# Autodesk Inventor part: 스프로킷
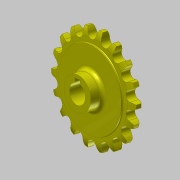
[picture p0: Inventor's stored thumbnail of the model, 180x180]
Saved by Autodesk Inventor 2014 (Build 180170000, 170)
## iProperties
Created: 2016-03
Part Number: 스프로킷
Material: 강철, 탄소
Document SubType Name: Modeling
Designer: mduedu
Density: 7.87 g/cm^3
Mass: 301.818 g
Surface Area: 124.882 cm^2
Volume: 38.3505 cm^3
Appearance: Smooth - Yellow
Author: mduedu
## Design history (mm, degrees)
sketch "스케치1"
  geometry: L1 (0, 5)-(29.5, 5); L2 (29.5, 5)-(29.5, 4.1); L3 (30, 3.6)-(33.625, 3.6); L4 (40, 2)-(40, 0); L5 (40, 0)-(0, 0); L6 (0, 0)-(0, 5); L7 (0, -5)-(29.5, -5); L8 (29.5, -5)-(29.5, -4.1); L9 (30, -3.6)-(33.625, -3.6); L10 (40, -2)-(40, 0); L11 (0, 0)-(0, -5); A1 r 13.5 centre (33.625, -9.9) between (40, 2) and (33.625, 3.6); A2 r 13.5 centre (33.625, 9.9) between (33.625, -3.6) and (40, -2); A3 r 0.5 centre (30, 4.1) between (29.5, 4.1) and (30, 3.6); A4 r 0.5 centre (30, -4.1) between (30, -3.6) and (29.5, -4.1); 2 further points
  constraints: 22 end point, 8 point on circle, 6 symmetric about line, 5 tangent, 4 centre point, 4 parallel, 4 point on line, 1 equal radius, 1 horizontal, 1 perpendicular, 1 other
  dimensions: "d0" = 80 diameter of L4 L6; "d2" = 59 diameter of L2 L6; "d3" = 1.6 vertical distance of L4.start L3.end; "d4" = 3.6 distance from line of L4.end L3; "d5" = 5 distance between parallel lines of L5 L1; "d6" = 13.5 radius of A1; "d15" = 0.5 radius of A3
revolve "회전1" sketch "스케치1" stored, may be unused: angle "d7" = 90 deg
sketch "스케치2" dims "d8" = 65.2, "d11" = 80
  geometry: L1 (0, 0)-(0, 32.6); A1 r 36.57 centre (0, 0) between (-16.231, 32.771) and (0, 36.57); A2 r 3.97 centre (0, 36.57) between (-3.866, 35.665) and (0, 32.6); A3 r 12.7 centre (-16.231, 32.771) between (-3.866, 35.665) and (-5.534, 39.615); A4 r 12.7 centre (16.231, 32.771) between (5.534, 39.615) and (3.866, 35.665); A5 r 3.97 centre (0, 36.57) between (0, 32.6) and (3.866, 35.665); A6 r 40 centre (0, 0) between (5.534, 39.615) and (-5.534, 39.615); 2 further points
  constraints: 12 point on circle, 6 centre point, 4 coincident, 3 symmetric about line, 2 end point, 1 point on line, 1 tangent, 1 vertical, 1 vertical alignment, 7 other
  dimensions: "d10" = 73.14 diameter of A1; "d12" = 12.7 radius of A3
extrude "돌출1" cut sketch "스케치2" stored distance "d13" = 10; taper "d14" = 0 deg
sketch "스케치3"
  geometry: C1 r 12.5 at (0, 0); 1 further point
  constraints: 1 centre point, 1 coincident
  dimensions: "d19" = 25 diameter of C1
extrude "돌출2" join sketch "스케치3" distance "d20" = 10; taper "d21" = 0 deg
fillet "모깎기1" dims "d22" = 3
sketch "스케치4"
  geometry: L1 (-2.5, 0)-(2.5, 0); L2 (2.5, 0)-(2.5, 9.8); L3 (2.5, 9.8)-(-2.5, 9.8); L4 (-2.5, 9.8)-(-2.5, 0); C1 r 7.5 at (0, 0); 2 further points
  constraints: 8 end point, 2 coincident, 2 parallel, 1 centre point, 1 horizontal, 1 midpoint, 1 perpendicular
  dimensions: "d23" = 15 diameter of C1; "d25" = 5 distance of L2.end L3.end; "d26" = 9.8 distance of L1.end L2.end
extrude "돌출3" cut sketch "스케치4" stored distance "d27" = 8; taper "d28" = 0 deg
node "솔리드1"
pattern_circular "원형 패턴1" dims angle "d17" = 360 deg
